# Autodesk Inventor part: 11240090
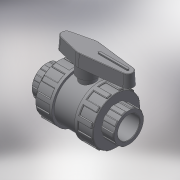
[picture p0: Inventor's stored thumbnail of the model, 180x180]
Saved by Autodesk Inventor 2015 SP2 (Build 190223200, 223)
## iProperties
Created: 2017-11
Part Number: 11240090
Material: Generic
Description: PLASSON BI STOP VALVE CEM PVC 90
Document SubType Name: Modeling
Designer: KIM
Density: 1 g/cm^3
Appearance: Default
Author: KIM
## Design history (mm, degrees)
derived "112400 - 112700.ipt"
feature "Solid1::112400 - 112700.ipt"
tag "TaggingFeature1"
body "Solid1"
other parameters: "d2" = 165, "d3" = 51, "d4" = 72, "d5" = 35.7, "d7" = 126, "d8" = 148.5, "d13" = 2.7, "d23" = 51, "d24" = 158.4, "d25" = 1.8, "d26" = 2.7, "d27" = 24.75, "d28" = 12.375, "d29" = 38.25, "d30" = 0, "d35" = 2.7, "d39" = 82.5, "d45" = 360 deg, "d47" = 1.8, "d50" = 90.75, "d51" = 49.5, "d53" = 0, "d55" = 18, "d56" = 9, "d57" = 35.7, "d58" = 0, "d59" = 2.7, "d61" = 360 deg, "d63" = 66, "d64" = 146, "d66" = 153, "d68" = 33, "d69" = 45.9, "d70" = 36.5, "d71" = 3 deg, "d73" = 3.3, "d74" = 61.2, "d75" = 4.38, "d76" = 0, "d77" = 1.8, "l_" = 51, "K_" = 165, "F_" = 146, "J_" = 153, "d67" = 66, "d72" = 16.5
